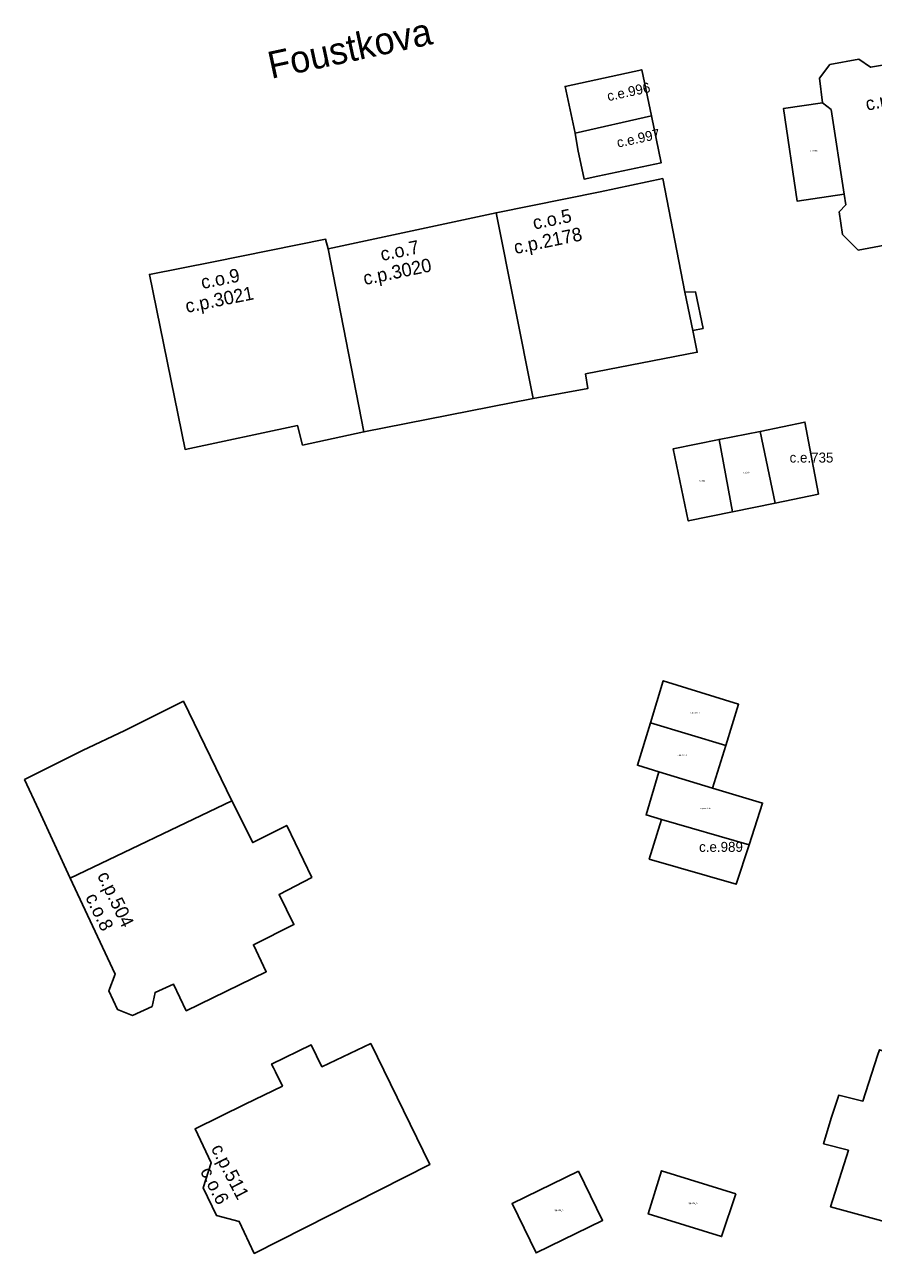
# Model space of a CAD drawing. Extents: x -600391 to -599491, y -1160176 to -1159402.
# Drawn here: x -600068.7 to -600005.8, y -1159576.2 to -1159485.1 of the extents above; entities that cross this region are included whole.
import ezdxf

# ---------------------------------------------------------------- set-up
doc = ezdxf.new("R2010")
doc.units = 0
for name, color, linetype in [('Level 10', 7, 'Continuous'), ('Level 11', 7, 'Continuous'), ('Level 12', 7, 'Continuous'), ('Level 23', 7, 'Continuous'), ('Level 24', 7, 'Continuous'), ('Level 25', 7, 'Continuous'), ('Level 61', 7, 'Continuous'), ('Level 62', 7, 'Continuous')]:
    doc.layers.add(name, color=color, linetype=linetype)

msp = doc.modelspace()

# ---------------------------------------------------------------- linework, layer by layer
at = {"layer": 'Level 61'}
for points in [[(-600009.76, -1159489.08), (-600008.99, -1159488.05)], [(-600008.99, -1159488.05), (-600006.84, -1159487.66)], [(-600006.84, -1159487.66), (-600005.98, -1159488.26)], [(-600005.98, -1159488.26), (-600003.32, -1159487.81)], [(-600028.63, -1159489.68), (-600022.94, -1159488.45)], [(-600022.94, -1159488.45), (-600022.23, -1159491.86)], [(-600009.54, -1159490.89), (-600009.76, -1159489.08)], [(-600027.87, -1159493.14), (-600028.63, -1159489.68)], [(-600012.44, -1159491.33), (-600009.54, -1159490.89)], [(-600008.91, -1159491.4), (-600009.54, -1159490.89)], [(-600009.54, -1159490.89), (-600008.91, -1159491.4)], [(-600022.23, -1159491.86), (-600027.87, -1159493.14)], [(-600027.87, -1159493.14), (-600022.23, -1159491.86)], [(-600022.23, -1159491.86), (-600021.51, -1159495.35)], [(-600011.42, -1159498.2), (-600012.44, -1159491.33)], [(-600007.93, -1159497.67), (-600008.91, -1159491.4)], [(-600008.91, -1159491.4), (-600007.93, -1159497.67)], [(-600027.69, -1159494.36), (-600027.87, -1159493.14)], [(-600027.22, -1159496.55), (-600027.69, -1159494.36)], [(-600021.51, -1159495.35), (-600026.19, -1159496.33)], [(-600026.19, -1159496.33), (-600027.22, -1159496.55)], [(-600026.03, -1159497.49), (-600021.39, -1159496.52)], [(-600021.39, -1159496.52), (-600019.75, -1159504.94)], [(-600033.74, -1159499.05), (-600026.03, -1159497.49)], [(-600007.93, -1159497.67), (-600011.42, -1159498.2)], [(-600007.82, -1159498.47), (-600007.93, -1159497.67)], [(-600046.18, -1159501.73), (-600033.74, -1159499.05)], [(-600033.74, -1159499.05), (-600030.99, -1159512.8)], [(-600030.99, -1159512.8), (-600033.74, -1159499.05)], [(-600008.3, -1159498.98), (-600007.82, -1159498.47)], [(-600008.07, -1159500.65), (-600008.3, -1159498.98)], [(-600054.68, -1159502.68), (-600046.38, -1159501.01)], [(-600046.38, -1159501.01), (-600046.18, -1159501.73)], [(-600006.89, -1159501.81), (-600008.07, -1159500.65)], [(-600046.18, -1159501.73), (-600043.54, -1159515.29)], [(-600043.54, -1159515.29), (-600046.18, -1159501.73)], [(-600004.93, -1159501.44), (-600006.89, -1159501.81)], [(-600059.44, -1159503.62), (-600054.68, -1159502.68)], [(-600056.79, -1159516.58), (-600059.44, -1159503.62)], [(-600019.75, -1159504.94), (-600018.96, -1159504.9)], [(-600019.75, -1159504.94), (-600019.16, -1159507.77)], [(-600019.16, -1159507.77), (-600019.75, -1159504.94)], [(-600018.96, -1159504.9), (-600018.4, -1159507.62)], [(-600018.4, -1159507.62), (-600019.16, -1159507.77)], [(-600019.16, -1159507.77), (-600018.83, -1159509.38)], [(-600018.83, -1159509.38), (-600027.1, -1159510.99)], [(-600027.1, -1159510.99), (-600026.95, -1159512.08)], [(-600030.99, -1159512.8), (-600043.54, -1159515.29)], [(-600026.95, -1159512.08), (-600030.99, -1159512.8)], [(-600014.16, -1159515.25), (-600010.85, -1159514.56)], [(-600010.85, -1159514.56), (-600009.85, -1159519.9)], [(-600048.45, -1159514.82), (-600056.79, -1159516.58)], [(-600048.08, -1159516.27), (-600048.45, -1159514.82)], [(-600043.54, -1159515.29), (-600048.08, -1159516.27)], [(-600017.21, -1159515.84), (-600014.16, -1159515.25)], [(-600013.06, -1159520.58), (-600014.16, -1159515.25)], [(-600014.16, -1159515.25), (-600013.06, -1159520.58)], [(-600020.62, -1159516.55), (-600017.21, -1159515.84)], [(-600019.5, -1159521.88), (-600020.62, -1159516.55)], [(-600016.22, -1159521.21), (-600017.21, -1159515.84)], [(-600017.21, -1159515.84), (-600016.22, -1159521.21)], [(-600009.85, -1159519.9), (-600013.06, -1159520.58)], [(-600013.06, -1159520.58), (-600016.22, -1159521.21)], [(-600016.22, -1159521.21), (-600019.5, -1159521.88)], [(-600022.29, -1159536.84), (-600021.35, -1159533.73)], [(-600021.35, -1159533.73), (-600015.76, -1159535.47)], [(-600061.27, -1159537.42), (-600056.92, -1159535.25)], [(-600056.92, -1159535.25), (-600053.32, -1159542.62)], [(-600015.76, -1159535.47), (-600016.71, -1159538.53)], [(-600064.39, -1159538.9), (-600061.27, -1159537.42)], [(-600023.27, -1159539.99), (-600022.29, -1159536.84)], [(-600022.29, -1159536.84), (-600016.71, -1159538.53)], [(-600016.71, -1159538.53), (-600022.29, -1159536.84)], [(-600068.69, -1159541.06), (-600064.39, -1159538.9)], [(-600016.71, -1159538.53), (-600017.69, -1159541.68)], [(-600021.68, -1159540.47), (-600023.27, -1159539.99)], [(-600067.64, -1159543.33), (-600068.69, -1159541.06)], [(-600022.62, -1159543.67), (-600021.68, -1159540.47)], [(-600017.69, -1159541.68), (-600021.68, -1159540.47)], [(-600021.68, -1159540.47), (-600017.69, -1159541.68)], [(-600017.69, -1159541.68), (-600013.99, -1159542.79)], [(-600053.32, -1159542.62), (-600065.3, -1159548.36)], [(-600065.3, -1159548.36), (-600053.32, -1159542.62)], [(-600053.32, -1159542.62), (-600051.78, -1159545.72)], [(-600013.99, -1159542.79), (-600014.97, -1159545.88)], [(-600065.3, -1159548.36), (-600067.64, -1159543.33)], [(-600021.47, -1159544.01), (-600022.62, -1159543.67)], [(-600051.78, -1159545.72), (-600049.26, -1159544.45)], [(-600049.26, -1159544.45), (-600047.4, -1159548.31)], [(-600022.39, -1159546.95), (-600021.47, -1159544.01)], [(-600021.47, -1159544.01), (-600014.97, -1159545.88)], [(-600014.97, -1159545.88), (-600021.47, -1159544.01)], [(-600014.97, -1159545.88), (-600015.95, -1159548.81)], [(-600015.95, -1159548.81), (-600022.39, -1159546.95)], [(-600065.13, -1159548.72), (-600065.3, -1159548.36)], [(-600047.4, -1159548.31), (-600049.82, -1159549.57)], [(-600061.97, -1159555.47), (-600065.13, -1159548.72)], [(-600049.82, -1159549.57), (-600048.73, -1159551.8)], [(-600048.73, -1159551.8), (-600051.73, -1159553.29)], [(-600051.73, -1159553.29), (-600050.78, -1159555.3)], [(-600062.45, -1159556.72), (-600061.97, -1159555.47)], [(-600050.78, -1159555.3), (-600056.71, -1159558.18)], [(-600057.66, -1159556.21), (-600059.01, -1159556.83)], [(-600056.71, -1159558.18), (-600057.66, -1159556.21)], [(-600061.8, -1159558.1), (-600062.45, -1159556.72)], [(-600059.01, -1159556.83), (-600059.24, -1159557.87)], [(-600060.68, -1159558.53), (-600061.8, -1159558.1)], [(-600059.24, -1159557.87), (-600060.68, -1159558.53)], [(-600050.38, -1159562.14), (-600047.45, -1159560.7)], [(-600047.45, -1159560.7), (-600046.65, -1159562.33)], [(-600046.65, -1159562.33), (-600043.03, -1159560.62)], [(-600043.03, -1159560.62), (-600038.66, -1159569.59)], [(-600006.55, -1159564.88), (-600005.47, -1159561.49)], [(-600050.25, -1159562.41), (-600050.38, -1159562.14)], [(-600050.09, -1159562.72), (-600050.25, -1159562.41)], [(-600049.58, -1159563.77), (-600050.09, -1159562.72)], [(-600052.35, -1159565.12), (-600049.58, -1159563.77)], [(-600008.9, -1159566.14), (-600008.34, -1159564.45)], [(-600008.34, -1159564.45), (-600006.55, -1159564.88)], [(-600056.05, -1159566.93), (-600052.35, -1159565.12)], [(-600009.46, -1159568.04), (-600008.9, -1159566.14)], [(-600054.85, -1159569.45), (-600056.05, -1159566.93)], [(-600007.63, -1159568.53), (-600009.46, -1159568.04)], [(-600008.94, -1159572.71), (-600007.63, -1159568.53)], [(-600055.44, -1159571.3), (-600054.85, -1159569.45)], [(-600038.66, -1159569.59), (-600051.66, -1159576.17)], [(-600032.55, -1159572.48), (-600027.63, -1159570.08)], [(-600027.63, -1159570.08), (-600025.85, -1159573.73)], [(-600022.46, -1159573.24), (-600021.49, -1159570.04)], [(-600021.49, -1159570.04), (-600015.97, -1159571.76)], [(-600054.46, -1159573.36), (-600055.44, -1159571.3)], [(-600015.97, -1159571.76), (-600017.02, -1159574.92)], [(-600030.77, -1159576.13), (-600032.55, -1159572.48)], [(-600001.17, -1159574.85), (-600008.94, -1159572.71)], [(-600052.78, -1159573.8), (-600054.46, -1159573.36)], [(-600051.66, -1159576.17), (-600052.78, -1159573.8)], [(-600025.85, -1159573.73), (-600030.77, -1159576.13)], [(-600017.02, -1159574.92), (-600022.46, -1159573.24)]]:
    msp.add_lwpolyline(points, dxfattribs=at)
at = {"layer": 'Level 62'}
for points in [[(-600003.32, -1159487.81), (-600002.83, -1159487.73), (-600001.12, -1159487.44), (-600000.82, -1159487.37), (-599997.74, -1159486.86), (-599995.81, -1159499.5), (-599996.15, -1159499.56), (-599998.59, -1159499.97), (-599999.19, -1159500.08), (-600000.14, -1159500.24), (-600004.68, -1159501.02), (-600004.93, -1159501.44), (-600006.89, -1159501.81), (-600008.07, -1159500.65), (-600008.3, -1159498.98), (-600007.82, -1159498.47), (-600007.93, -1159497.67), (-600008.91, -1159491.4), (-600009.54, -1159490.89), (-600009.76, -1159489.08), (-600008.99, -1159488.05), (-600006.84, -1159487.66), (-600005.98, -1159488.26), (-600003.32, -1159487.81)], [(-600027.87, -1159493.14), (-600028.63, -1159489.68), (-600022.94, -1159488.45), (-600022.23, -1159491.86), (-600027.87, -1159493.14)], [(-600007.93, -1159497.67), (-600011.42, -1159498.2), (-600012.44, -1159491.33), (-600009.54, -1159490.89), (-600008.91, -1159491.4), (-600007.93, -1159497.67)], [(-600027.87, -1159493.14), (-600022.23, -1159491.86), (-600021.51, -1159495.35), (-600026.19, -1159496.33), (-600027.22, -1159496.55), (-600027.69, -1159494.36), (-600027.87, -1159493.14)], [(-600019.16, -1159507.77), (-600018.83, -1159509.38), (-600027.1, -1159510.99), (-600026.95, -1159512.08), (-600030.99, -1159512.8), (-600033.74, -1159499.05), (-600026.03, -1159497.49), (-600021.39, -1159496.52), (-600019.75, -1159504.94), (-600019.16, -1159507.77)], [(-600033.74, -1159499.05), (-600030.99, -1159512.8), (-600043.54, -1159515.29), (-600046.18, -1159501.73), (-600033.74, -1159499.05)], [(-600046.18, -1159501.73), (-600043.54, -1159515.29), (-600048.08, -1159516.27), (-600048.45, -1159514.82), (-600056.79, -1159516.58), (-600059.44, -1159503.62), (-600054.68, -1159502.68), (-600046.38, -1159501.01), (-600046.18, -1159501.73)], [(-600019.16, -1159507.77), (-600019.75, -1159504.94), (-600018.96, -1159504.9), (-600018.4, -1159507.62), (-600019.16, -1159507.77)], [(-600014.16, -1159515.25), (-600010.85, -1159514.56), (-600009.85, -1159519.9), (-600013.06, -1159520.58), (-600014.16, -1159515.25)], [(-600016.22, -1159521.21), (-600017.21, -1159515.84), (-600014.16, -1159515.25), (-600013.06, -1159520.58), (-600016.22, -1159521.21)], [(-600016.22, -1159521.21), (-600019.5, -1159521.88), (-600020.62, -1159516.55), (-600017.21, -1159515.84), (-600016.22, -1159521.21)], [(-600022.29, -1159536.84), (-600021.35, -1159533.73), (-600015.76, -1159535.47), (-600016.71, -1159538.53), (-600022.29, -1159536.84)], [(-600061.27, -1159537.42), (-600056.92, -1159535.25), (-600053.32, -1159542.62), (-600065.3, -1159548.36), (-600067.64, -1159543.33), (-600068.69, -1159541.06), (-600064.39, -1159538.9), (-600061.27, -1159537.42)], [(-600022.29, -1159536.84), (-600016.71, -1159538.53), (-600017.69, -1159541.68), (-600021.68, -1159540.47), (-600023.27, -1159539.99), (-600022.29, -1159536.84)], [(-600017.69, -1159541.68), (-600013.99, -1159542.79), (-600014.97, -1159545.88), (-600021.47, -1159544.01), (-600022.62, -1159543.67), (-600021.68, -1159540.47), (-600017.69, -1159541.68)], [(-600065.13, -1159548.72), (-600065.3, -1159548.36), (-600053.32, -1159542.62), (-600051.78, -1159545.72), (-600049.26, -1159544.45), (-600047.4, -1159548.31), (-600049.82, -1159549.57), (-600048.73, -1159551.8), (-600051.73, -1159553.29), (-600050.78, -1159555.3), (-600056.71, -1159558.18), (-600057.66, -1159556.21), (-600059.01, -1159556.83), (-600059.24, -1159557.87), (-600060.68, -1159558.53), (-600061.8, -1159558.1), (-600062.45, -1159556.72), (-600061.97, -1159555.47), (-600065.13, -1159548.72)], [(-600021.47, -1159544.01), (-600014.97, -1159545.88), (-600015.95, -1159548.81), (-600022.39, -1159546.95), (-600021.47, -1159544.01)], [(-600050.09, -1159562.72), (-600050.25, -1159562.41), (-600050.38, -1159562.14), (-600047.45, -1159560.7), (-600046.65, -1159562.33), (-600043.03, -1159560.62), (-600038.66, -1159569.59), (-600051.66, -1159576.17), (-600052.78, -1159573.8), (-600054.46, -1159573.36), (-600055.44, -1159571.3), (-600054.85, -1159569.45), (-600056.05, -1159566.93), (-600052.35, -1159565.12), (-600049.58, -1159563.77), (-600050.09, -1159562.72)], [(-600005.47, -1159561.49), (-600005.33, -1159561.08), (-599993.08, -1159564.94), (-599993.19, -1159565.41), (-599994.52, -1159569.67), (-599994.21, -1159570.25), (-599995.6, -1159574.7), (-600000.69, -1159573.38), (-600001.17, -1159574.85), (-600008.94, -1159572.71), (-600007.63, -1159568.53), (-600009.46, -1159568.04), (-600008.9, -1159566.14), (-600008.34, -1159564.45), (-600006.55, -1159564.88), (-600005.47, -1159561.49)], [(-600027.63, -1159570.08), (-600025.85, -1159573.73), (-600030.77, -1159576.13), (-600032.55, -1159572.48), (-600027.63, -1159570.08)], [(-600015.97, -1159571.76), (-600017.02, -1159574.92), (-600022.46, -1159573.24), (-600021.49, -1159570.04), (-600015.97, -1159571.76)]]:
    msp.add_lwpolyline(points, dxfattribs=at)

# ---------------------------------------------------------------- texts
at = {"layer": 'Level 10'}
for s, rotation, p in [('c.o.5', 11.66615, (-600030.913, -1159500.298)), ('c.o.7', 11.63017, (-600042.204, -1159502.626)), ('c.o.9', 11.43804, (-600055.511, -1159504.706)), ('c.o.8', 295.62716, (-600064.211, -1159549.765)), ('c.o.6', 297.29793, (-600055.702, -1159570.079))]:
    msp.add_text(s, height=1, rotation=rotation, dxfattribs=at).set_placement(p)
at = {"layer": 'Level 11'}
msp.add_text('Foustkova', height=2, rotation=12.15283, dxfattribs=at).set_placement((-600050.411, -1159489.127))
at = {"layer": 'Level 12'}
for s, rotation, p in [('c.p.542', 11.85266, (-600006.244, -1159491.494)), ('c.p.2178', 11.66615, (-600032.313, -1159502.118)), ('c.p.3020', 11.63017, (-600043.48, -1159504.412)), ('c.p.3021', 11.43804, (-600056.667, -1159506.473)), ('c.p.504', 295.62716, (-600063.329, -1159548.156)), ('c.p.511', 297.29793, (-600054.897, -1159568.385))]:
    msp.add_text(s, height=1, rotation=rotation, dxfattribs=at).set_placement(p)
at = {"layer": 'Level 23'}
for s, p in [('c.e.996', (-600025.426, -1159490.782)), ('c.e.997', (-600024.707, -1159494.226))]:
    msp.add_text(s, height=0.74, rotation=12.1979, dxfattribs=at).set_placement(p)
for s, p in [('c.e.735', (-600011.983, -1159517.559)), ('c.e.989', (-600018.693, -1159546.411))]:
    msp.add_text(s, height=0.74, dxfattribs=at).set_placement(p)
at = {"layer": 'Level 24'}
for s, p in [('c.z.1970', (-600010.444, -1159494.507)), ('c.z.273', (-600015.409, -1159518.347)), ('c.z.513', (-600018.699, -1159518.947))]:
    msp.add_text(s, height=0.1, dxfattribs=at).set_placement(p)
at = {"layer": 'Level 25'}
for s, p in [('c.pp.337_B', (-600019.323, -1159536.147)), ('c.pp.337_A', (-600020.293, -1159539.277)), ('c.pp.2579_B', (-600018.618, -1159543.227)), ('c.pp.536_A', (-600029.458, -1159573.015)), ('c.pp.521_A', (-600019.523, -1159572.497))]:
    msp.add_text(s, height=0.1, dxfattribs=at).set_placement(p)

doc.saveas('drawing.dxf')
